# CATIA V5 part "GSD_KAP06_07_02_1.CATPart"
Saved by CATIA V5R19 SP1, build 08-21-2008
Part number: GSD_SWEEP_LINE_01
Definition: Beispielmodell für die Funktion Translation - Linie / Sweep - Line.
Description: CATIA V5 Flächenmodellierung  Copyright (c) 2009 Maik Hertha IT Consultants
Bounding box of the stored display mesh (mm): x -120.631 to 113.287, y -63.498 to -3.164, z -40 to 0
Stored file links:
  \GSD_BUCH_UEBUNG\GSD_KAP06_07_02_1.CATPart
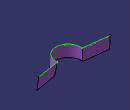
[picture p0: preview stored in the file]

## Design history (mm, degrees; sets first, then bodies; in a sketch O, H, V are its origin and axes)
AxisSystem1: origin (0, 0, 0), X (1, 0, 0), Y (0, 1, 0), Z (0, 0, 1)
Set1
  Sketch1 on xy-plane, origin (0, 0, 0), H (1, 0, 0), V (0, 1, 0)
    line L1 (112.3223, -3.1639) -> (39.7788, -15.7993)
    arc A1 centre (0, -20) radius 40 from (39.7788, -15.7993) to (-39.6088, -14.4195) cw
    point P3 (0, -20)
    line L2 (-39.6088, -14.4195) -> (-120.363, -4.0213)
    construction line L3 (13.9125, -20) -> (-11.1781, -20)
    construction line L4 (39.2477, 0) -> (-28.2488, 0)
    point P8 (39.2477, 0)
    construction line L5 (0, 7.9755) -> (0, -63.4676)
    point P10 (0, 7.9755)
    curve C1
    spline S1 through (-120.9377, -13.3542) (-46.9511, -26.3635) (48.4251, -27.4184) (115.1771, -16.8703)
    curve C2
    distance L3 L4 = 20
    radius A1 = 40
    horizontal: L3 H, L4 H
    coincidence: P8 H, P10 V, P3 L5, P3 L3
    vertical: L5 V
Set2
  DatumCurve1: linked copy from another document
  Sweep1: type Segment, Angle 3, Length1 40, Length2 0, DraftDirection (0, 0, 1), DraftAngleLoc (edge of DatumCurve1; edge of DatumCurve1; edge of DatumCurve1), Angle##1## 3, Angle##2## 5, Angle##3## 8, GuideCrv DatumCurve1
Set3
  DatumCurve2: linked copy from another document
Body1 (main body)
